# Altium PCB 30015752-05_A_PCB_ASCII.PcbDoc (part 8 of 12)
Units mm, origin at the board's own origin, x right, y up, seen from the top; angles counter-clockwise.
Board outline 100.05 x 72 mm, 10 copper layers (Top, GND_2, Signal_3, Signal_4, PWR_5, GND_6, Signal_7, Signal_8, GND_9, Bottom), stack 1.493 mm thick; 577 components, 546 nets, 2389 pads, 1412 vias.
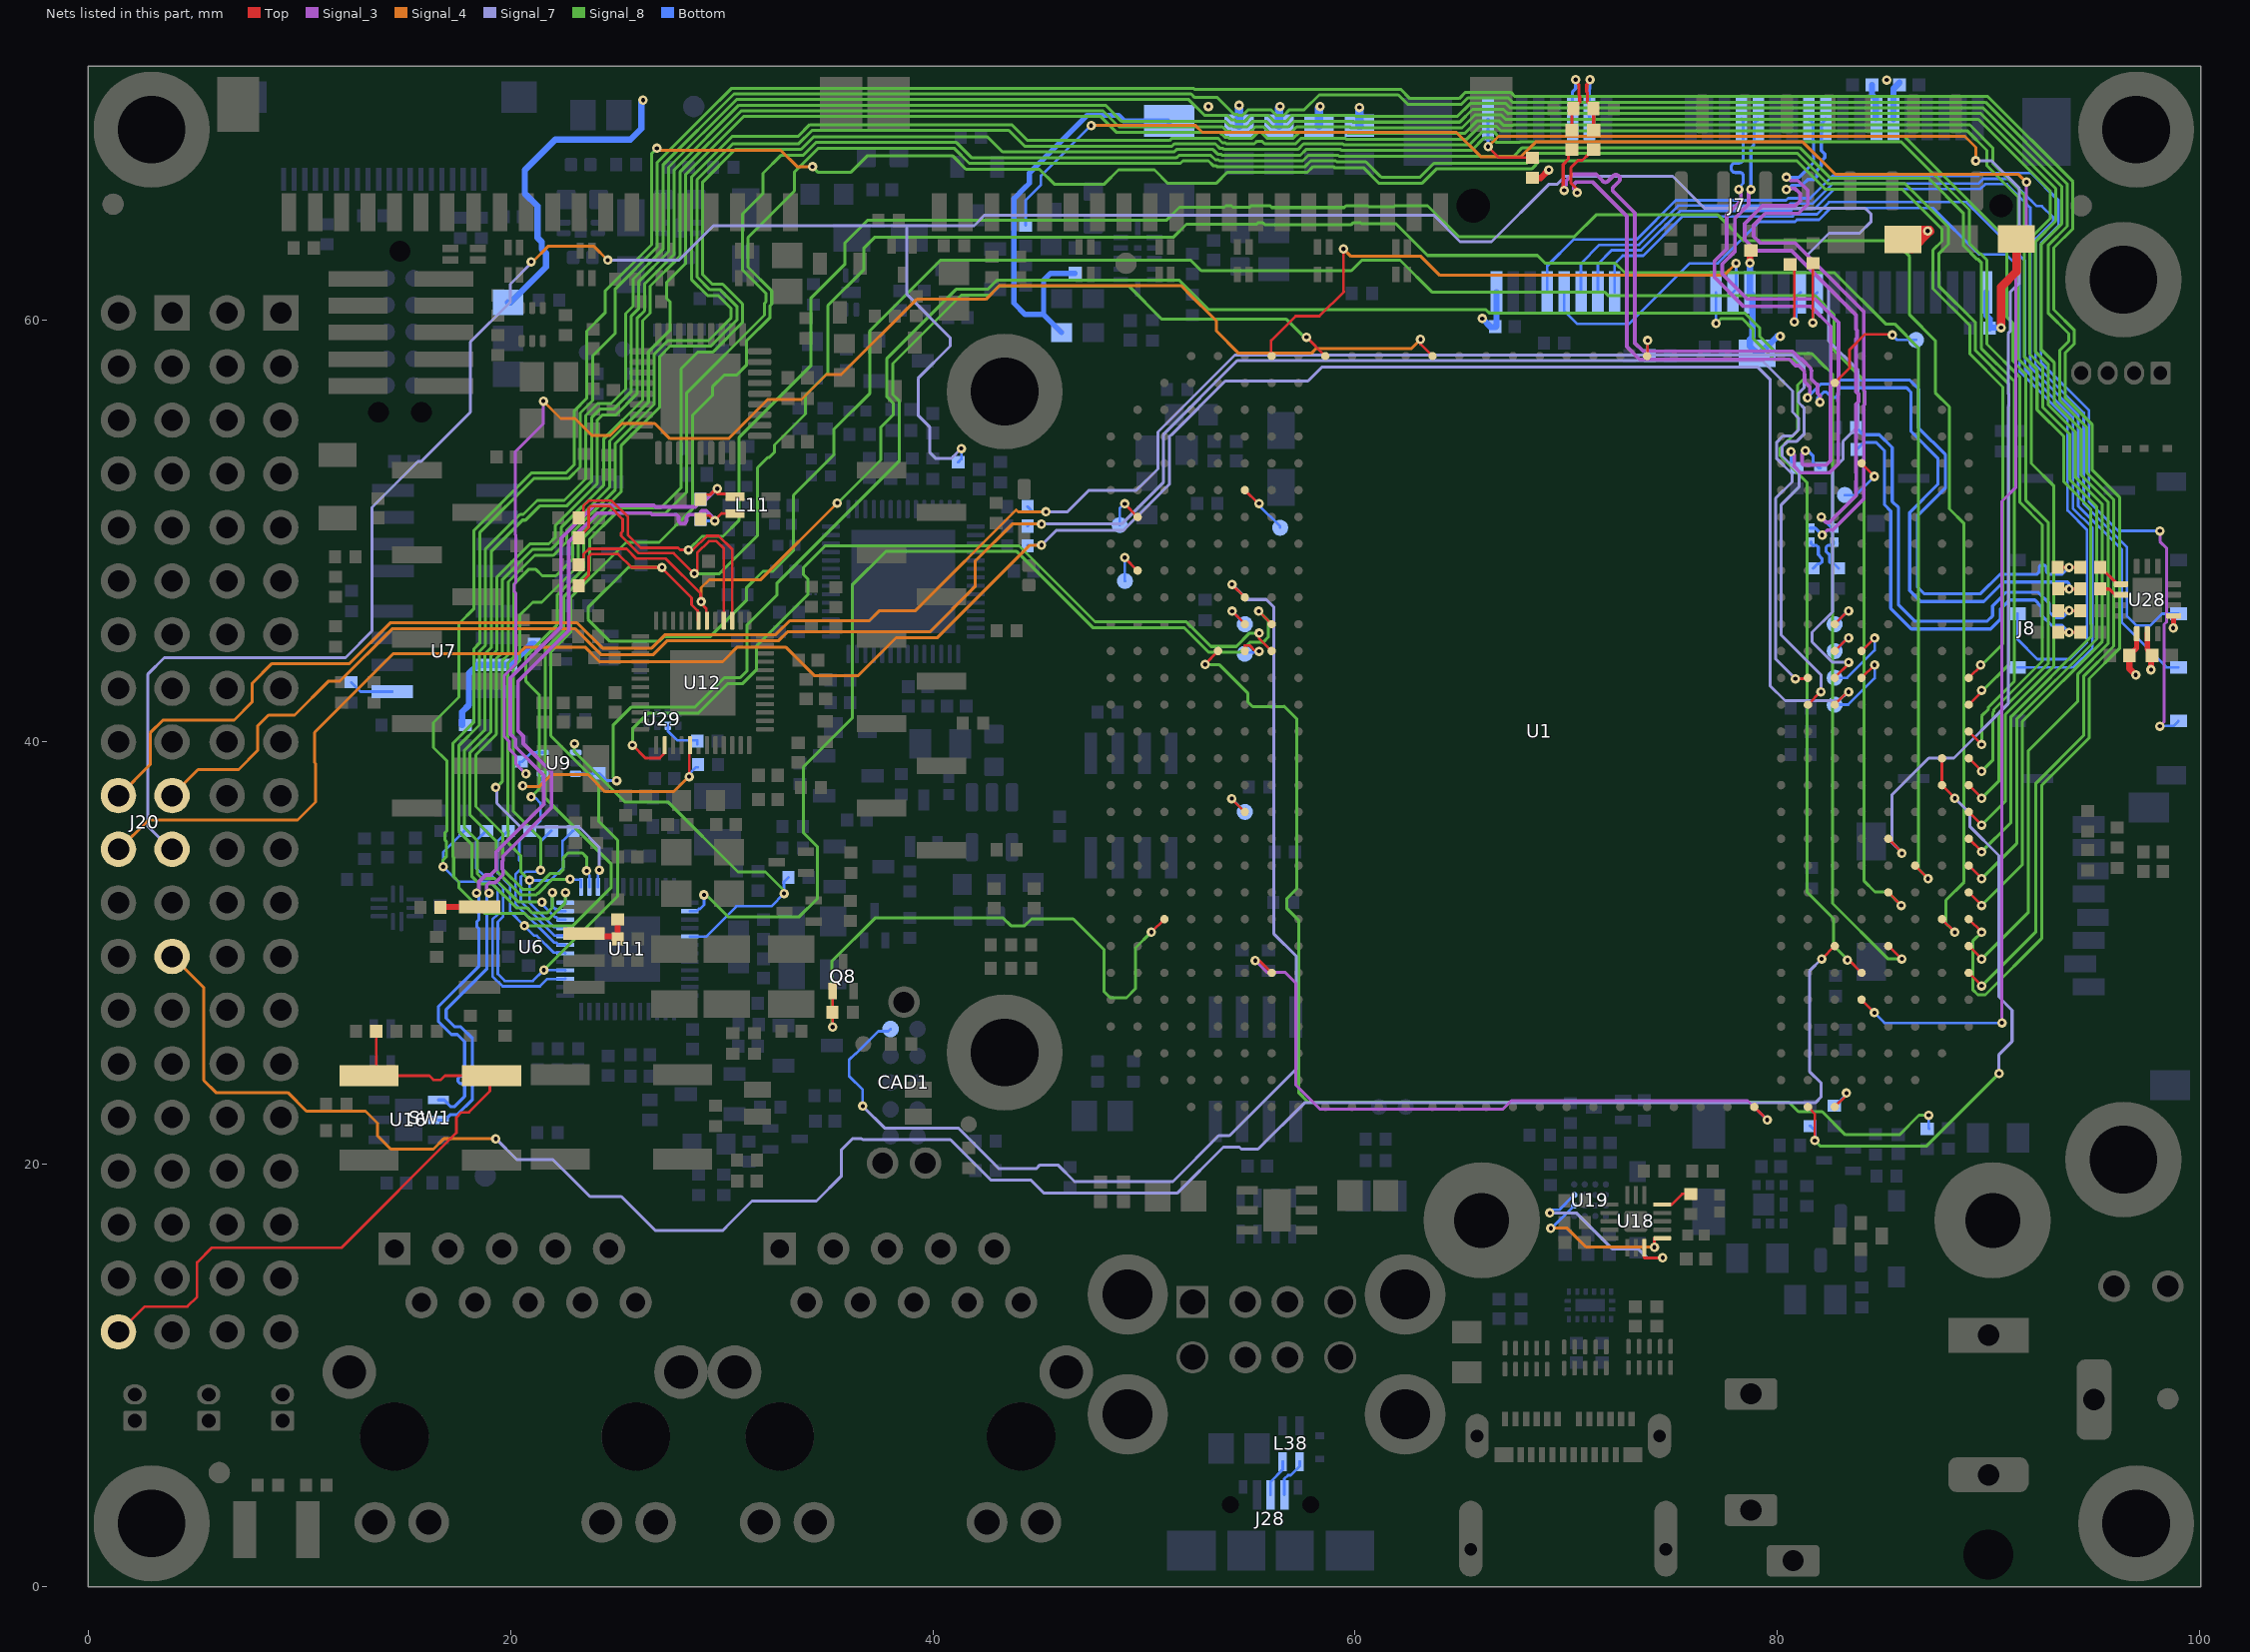
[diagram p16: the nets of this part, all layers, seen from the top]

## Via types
v1: diameter 0.45, hole 0.2, Top to Bottom, tented both sides, 1412 vias

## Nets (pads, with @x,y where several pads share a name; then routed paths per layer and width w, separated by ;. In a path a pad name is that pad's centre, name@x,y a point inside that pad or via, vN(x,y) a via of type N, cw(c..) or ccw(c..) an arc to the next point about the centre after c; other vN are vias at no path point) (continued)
NetR230_2: R230.2 R231.1 U1.N1 | length 1.5
  Top w0.127: U1.N1@73.83,58.28 73.86,58.31 v1(73.86,59.02)
  Bottom w0.127: v1(73.86,59.02) 73.86,58.46 73.83,58.43 R231.1@73.96,58.3
NetR232_2: R232.2 U1.F29 | length 1.7
  Top w0.127: U1.F29@82.72,22.72 83.275,23.275 v1(83.275,23.375)
  Bottom w0.127: R232.2@82.7,22.78 82.725,22.78 83.275,23.33 v1(83.275,23.375)
NetR234_1: R234.1 U18.5 | length 1.6
  Top w0.127: U18.5@74.55,18.1 75,18.1 75.5,18.6 R234.1@75.9,18.6
NetR236_1: R236.1 U28.8 | length 1.3
  Top w0.15: R236.1@95.305,48.275 96.105,47.475 U28.8@96.275,47.475
NetR237_1: R237.1 U28.9 | length 1.1
  Top w0.15: R237.1@95.305,47.25 95.725,47.25 96,46.975 U28.9@96.275,46.975
NetR244_2: R244.2 U29.6 | length 2
  Bottom w0.127: U29.6@27.45,40.775 27.45,40.525 27.9,40.075 28.845,40.075 R244.2@28.845,40.05 R244.2@28.845,39.9
NetR245_2: R245.2 R246.2 U6.3 | length 2.6
  Top w0.3: U6.3@23.47,30.925 23.595,30.8 24.945,30.8 R246.2@25.07,30.675 25.075,30.68 R245.2@25.075,31.595
NetR247_1: R247.1 U6.5 | length 1.9
  Top w0.3: R247.1@16.68,32.175 16.7,32.195 U6.5@18.53,32.195
NetR248_2: R248.2 R249.2 U7.3 | length 6.3
  Bottom w0.3: R248.2@17.7,40.805 17.7,41.425 18.025,41.75 18.025,43.25 18.431,43.656 U7.3@19.329,43.656 20.006,43.656 21.005,44.655 R249.2@21.125,44.655
NetR250_1: R250.1 U7.5 | length 2.1
  Bottom w0.127: R250.1@12.45,42.83 12.894,42.386 U7.5@14.389,42.386
NetTP3_1: TP3.1 U1.AH6 | length 2.5
  Top w0.127: U1.AH6@54.78,51.93 55.41,51.3 v1(55.45,51.3)
  Bottom w0.127: v1(55.45,51.3) 55.45,51.213 56.45,50.213 TP3.1@56.45,50.15
NetTP4_1: TP4.1 U1.AH11 | length 1.7
  Top w0.127: v1(54.175,46.2) 54.78,45.595 U1.AH11@54.78,45.58
  Bottom w0.127: v1(54.175,46.2) 54.175,46.193 54.78,45.588 TP4.1@54.78,45.58
NetTP5_1: TP5.1 U1.AH12 | length 1.8
  Top w0.127: U1.AH12@54.78,44.31 54.78,44.573 55.012,44.573 55.285,44.3 v1(55.45,44.3)
  Bottom w0.127: TP5.1@54.775,44.175 54.838,44.238 55.388,44.238 v1(55.45,44.3)
NetTP6_1: TP6.1 U1.AM7 | length 2
  Top w0.127: v1(49.09,51.28) 49.09,51.27 U1.AM7@49.7,50.66
  Bottom w0.127: TP6.1@48.85,50.275 48.85,51.057 49.073,51.28 v1(49.09,51.28)
NetTP7_1: TP7.1 U1.AM9 | length 2
  Top w0.127: v1(49.09,48.74) 49.09,48.73 U1.AM9@49.7,48.12
  Bottom w0.127: v1(49.09,48.74) 49.09,47.635 TP7.1@49.1,47.625
NetTP8_1: TP8.1 U1.F2 | length 5.4
  Top w0.127: U1.F2@82.72,57.01 83.425,57.715 83.425,58.575 84.162,59.312 85.413,59.312 v1(85.45,59.275)
  Bottom w0.127: v1(85.45,59.275) 85.677,59.048 TP8.1@86.575,59.048
NetTP9_1: TP9.1 U1.E5 | length 2.6
  Top w0.127: U1.E5@83.99,53.2 84.6,52.59 v1(84.6,52.58)
  Bottom w0.127: TP9.1@83.2,51.7 83.72,51.7 v1(84.6,52.58)
NetTP10_1: TP10.1 U1.AH18 | length 1.8
  Top w0.127: v1(54.16,37.32) 54.16,37.31 U1.AH18@54.78,36.69
  Bottom w0.127: v1(54.16,37.32) 54.16,37.315 54.78,36.695 TP10.1@54.78,36.69
NetTP18_1: TP18.1 U1.E13 | length 3.9
  Top w0.127: U1.E13@83.99,43.04 84.6,43.65 v1(84.61,43.65)
  Bottom w0.127: TP18.1@82.72,41.77 83.36,41.77 84.61,43.02 v1(84.61,43.65)
NetTP19_1: TP19.1 U1.E12 | length 3.9
  Top w0.127: U1.E12@83.99,44.31 84.6,44.92 v1(84.61,44.92)
  Bottom w0.127: TP19.1@82.72,43.04 83.303,43.04 84.61,44.347 v1(84.61,44.92)
NetTP20_1: TP20.1 U1.F12 | length 1.7
  Top w0.127: U1.F12@82.72,44.31 83.33,44.92 v1@83.34,44.92
  Bottom w0.127: TP20.1@82.72,44.31 82.725,44.31 83.335,44.92 v1@83.34,44.92
  other v1: 83.379,44.927
NetTP21_1: TP21.1 U1.F11 | length 1.7
  Top w0.127: U1.F11@82.72,45.58 83.33,46.19 v1@83.34,46.19
  Bottom w0.127: TP21.1@82.72,45.58 82.725,45.58 83.335,46.19 v1@83.34,46.19
  other v1: 83.379,46.202
NetU1_AG24: U1.AG24 U1.J29 | length 32.4
  Top w0.127: v1(55.275,29.65) 55.47,29.65 U1.AG24@56.05,29.07 ; U1.J29@78.91,22.72 79.52,22.11 v1(79.52,22.1)
  Signal_3 w0.142: v1(55.275,29.65) 55.825,29.1 56.675,29.1 57.2,28.575 57.2,23.75 58.333,22.617 66.997,22.617 67.398,23.019 78.601,23.019 v1(79.52,22.1)
NX5P3290_EN: U18.16 U19.B4 | length 9.1
  Top w0.127: U18.16@73.7,16.05 73.7,15.567 74.567,15.567 v1(74.575,15.575)
  Signal_7 w0.142: v1(69.225,17.7) 70.475,17.7 72.175,16 73.4,16 73.825,15.575 v1(74.575,15.575)
  Bottom w0.127: v1(69.225,17.7) 69.372,17.847 69.674,17.847 70.376,18.55 U19.B4@70.38,18.55
NX5P3290_FRS: U18.1 U19.C4 | length 7.7
  Top w0.127: v1(74.175,16.075) 74.175,16.475 74.2,16.5 U18.1@74.55,16.5
  Signal_4 w0.142: v1(69.275,16.975) 70.05,16.975 70.95,16.075 v1(74.175,16.075)
  Bottom w0.127: v1(69.275,16.975) 69.275,16.942 69.283,16.934 v1@69.288,16.939 ; v1@69.324,16.975 v1@69.288,16.939 ; U19.C4@70.38,18.05 69.278,16.948 v1@69.288,16.939
OTGD_N: J28.2 L38.2 | length 2
  Bottom w0.132: J28.2@56.65,4.35 56.65,5.104 56.828,5.282 56.957,5.282 57.375,5.7 L38.2@57.375,5.925
OTGD_P: J28.3 L38.3 | length 1.8
  Bottom w0.132: J28.3@56,4.35 56,4.975 56.575,5.55 L38.3@56.575,5.925
PCIe/EXPANSION_USB1_D_N: L11.2 R192.1 R229.1 U16.1 | length 44.8
  Top w0.132: R192.1@29.005,51.5 29.224,51.719 29.458,51.719 29.744,52.005 v1(29.788,52.005) 29.788,51.877 29.736,51.825 29.811,51.75 30.5,51.75 L11.2@30.625,51.625
  Signal_3 w0.175: v1(18.396,32.85) 18.5,32.954 18.5,33.378 18.833,33.71 19.057,33.71 19.308,33.961 19.308,34.482 19.315,34.489 19.315,34.79 21.575,37.05 21.575,38.429 20.232,39.772 20.232,40.132 19.992,40.371 19.992,43.042 22.382,45.432 22.382,49.632 23.958,51.208 26.785,51.208 26.857,51.135 28.74,51.135 28.938,51.334 29.117,51.334 v1(29.788,52.005)
  Bottom w0.132: R229.1@29.005,51.5 29.224,51.719 29.458,51.719 29.744,52.005 v1(29.788,52.005)
  Bottom w0.15: U16.1@16.575,23.05 16.85,23.05 17.175,22.725 17.329,22.725 17.825,23.221 17.825,23.65 17.825,23.667 ccw(c17.668,23.667) 17.668,23.825 cw(c17.668,23.982) 17.51,23.982 17.51,24.017 cw(c17.668,24.017) 17.668,24.175 ccw(c17.668,24.332) 17.825,24.332 17.825,24.625 17.825,25.804 17.479,26.15 17.197,26.15 16.582,26.766 16.582,27.478 18.5,29.396 18.5,31.15 18.4,31.25 18.4,31.5 18.5,31.6 18.5,31.9 18.325,32.075 18.325,32.25 18.5,32.425 18.5,32.746 v1(18.396,32.85)
PCIe/EXPANSION_USB1_D_P: L11.3 R191.1 R228.1 U16.2 | length 44.2
  Top w0.132: R191.1@29.005,50.55 29.18,50.725 29.425,50.725 29.613,50.538 29.65,50.5 v1@29.65,50.475 ; v1(29.675,50.475) v1@29.65,50.475 ; L11.3@30.625,50.825 30,50.825 29.662,50.487 v1@29.65,50.475
  Signal_3 w0.175: v1(18.973,32.85) 18.868,32.954 18.868,33.225 18.987,33.344 19.273,33.344 19.643,33.714 19.643,33.96 19.61,33.993 19.61,34.357 19.643,34.39 19.643,34.597 21.943,36.897 21.943,38.582 20.6,39.925 20.6,40.284 20.36,40.524 20.36,42.89 22.75,45.279 22.75,49.479 24.11,50.84 26.632,50.84 26.705,50.767 27.575,50.767 27.793,50.767 cw(c27.793,50.598) 27.962,50.598 27.962,50.51 ccw(c28.131,50.51) 28.131,50.342 28.169,50.342 ccw(c28.169,50.51) 28.337,50.51 28.337,50.598 cw(c28.506,50.598) 28.506,50.767 28.525,50.767 28.892,50.767 29.091,50.966 29.25,50.966 29.675,50.541 v1(29.675,50.475)
  Bottom w0.132: R228.1@29.005,50.45 29.03,50.475 v1(29.675,50.475)
  Bottom w0.15: U16.2@16.575,22.1 16.9,22.1 17.157,22.357 17.482,22.357 18.193,23.068 18.193,25.957 17.632,26.518 17.35,26.518 16.95,26.918 16.95,27.325 18.868,29.243 18.868,32.746 v1(18.973,32.85)
PCIE_CLK_N: C139.1 R195.2 R237.2 | length 49.8
  Top w0.15: v1(69.903,66.128) 69.903,66.203 69.85,66.256 69.886,66.293 69.857,66.322 69.857,67.353 70.106,67.602 C139.1@70.106,67.896 ; R195.2@93.28,47.25 R195.2@93.305,47.25 v1(93.825,47.25) R237.2@94.345,47.25
  Signal_3 w0.175: v1(69.903,66.128) 69.903,66.196 69.85,66.249 69.993,66.393 69.993,66.567 70.312,66.886 71.417,66.886 71.727,66.577 71.74,66.563 ccw(c71.859,66.683) 71.979,66.563 72.231,66.816 cw(c72.35,66.696) 72.47,66.816 72.496,66.789 cw(c72.377,66.67) 72.496,66.55 72.244,66.298 ccw(c72.363,66.178) 72.244,66.059 72.364,65.939 73.25,65.053 73.25,58.9 73.65,58.5 80.719,58.5 81.083,58.136 81.151,58.136 81.586,57.701 81.586,57.633 81.636,57.583 81.61,57.557 81.61,57.193 81.868,56.935 81.909,56.935 81.909,56.515 82.025,56.399 v1(82.025,56.1)
  Bottom w0.15: v1(82.025,56.1) 81.9,56.225 81.9,56.279 82.201,56.58 82.325,56.58 82.58,56.325 82.775,56.325 82.893,56.443 82.893,56.497 82.893,56.718 82.952,56.777 86.123,56.777 86.332,56.568 86.332,54.718 87.6,53.45 87.6,52.2 86.275,50.875 86.275,47.175 86.793,46.657 89.782,46.657 90.703,47.578 93.747,47.578 93.825,47.5 v1(93.825,47.25)
PCIE_CLK_P: C140.1 R112.2 R236.2 | length 48.5
  Top w0.15: v1(70.52,66.02) 70.52,66.18 70.225,66.475 70.225,67.2 70.575,67.55 70.77,67.55 71.059,67.84 71.075,67.84 C140.1@71.3,68.065 ; R112.2@93.28,48.275 v1(93.825,48.275) R236.2@94.345,48.275
  Signal_3 w0.175: 70.362,66.188 70.362,66.415 70.464,66.517 71.265,66.517 72.875,64.907 72.875,58.725 73.468,58.132 80.566,58.132 80.865,57.833 81.026,57.833 81.283,57.576 81.283,57.415 81.294,57.404 81.294,57.062 81.541,56.815 81.541,56.515 81.38,56.354 81.429,56.305 v1(81.429,56.303)
  Bottom w0.15: v1@81.4,56.3 v1@81.403,56.303 ; v1(81.429,56.303) v1@81.403,56.303 ; v1(93.825,48.275) 93.497,47.947 93.277,47.947 93.102,47.947 92.91,47.947 cw(c92.91,48.104) 92.752,48.104 92.752,48.226 ccw(c92.595,48.226) 92.595,48.383 92.56,48.383 ccw(c92.56,48.226) 92.402,48.226 92.402,48.104 cw(c92.245,48.104) 92.245,47.947 91.825,47.947 90.551,47.947 89.629,47.025 86.946,47.025 86.643,47.328 86.643,50.722 87.968,52.047 87.968,53.603 86.7,54.871 86.7,56.721 86.276,57.145 82.799,57.145 82.602,56.948 82.048,56.948 81.416,56.316 v1@81.403,56.303
PCIE_DIS_N: J7.20 U1.E24 | length 37.6
  Top w0.127: v1(83.325,29.675) 83.385,29.675 U1.E24@83.99,29.07
  Signal_8 w0.142: v1(77.1,59.825) 77.325,60.05 78.35,60.05 78.85,59.55 78.85,59.125 79.85,58.125 80.711,58.125 81.267,57.569 81.267,57.218 80.957,56.908 80.957,54.732 80.125,53.9 80.125,53.57 81.42,52.275 81.42,32.88 82.675,31.625 82.675,30.35 83.325,29.7 v1(83.325,29.675)
  Bottom w0.127: v1(77.1,59.825) J7.20@77.1,61.3
PCIE_I2C_SCL: J7.30 R177.2 | length 4.4
  Top w0.127: R177.2@80.6,62.62 80.8,62.42 80.76,62.38 80.804,62.336 v1(80.804,59.903)
  Bottom w0.127: v1(80.804,59.903) 80.889,59.987 80.889,61.089 J7.30@81.1,61.3
PCIE_I2C_SDA: J7.32 R178.2 | length 4.4
  Top w0.127: v1(81.686,59.86) 81.686,62.606 81.7,62.62 81.675,62.645 R178.2@81.7,62.67
  Bottom w0.127: v1(81.686,59.86) 81.689,59.862 81.689,61.089 J7.32@81.9,61.3
PCIE_RESET_N: J7.22 U1.AG1 | length 28
  Top w0.127: U1.AG1@56.05,58.28 56.024,58.306 56.024,59.012 57.186,60.174 58.312,60.174 59.475,61.337 59.453,61.359 v1(59.453,63.353)
  Signal_4 w0.142: v1(59.453,63.353) 59.806,63 63.122,63 64.018,62.104 77.479,62.104 v1(78.05,62.675)
  Bottom w0.127: J7.22@77.9,61.3 78.05,61.45 v1(78.05,62.675)
PCIE_RX_N: J7.23 R227.1 | length 25.1
  Signal_3 w0.175: v1(78.173,66.175) 78.277,66.071 78.277,65.652 77.6,64.975 77.6,63.35 77.025,62.775 77.025,62.015 78.413,60.627 81.598,60.627 82.532,59.693 82.532,56.86 82.525,56.853 82.525,53.325 82.325,53.125 81.247,53.125 81.172,53.2 81.172,53.647 v1(81.325,53.8)
  Bottom w0.15: v1@78.173,66.256 78.382,66.465 78.382,66.825 ccw(c78.231,66.825) 78.231,66.975 78.012,66.975 cw(c78.012,67.178) 77.81,67.178 77.81,67.223 cw(c78.012,67.223) 78.012,67.425 78.179,67.425 ccw(c78.179,67.628) 78.382,67.628 78.382,67.875 78.382,68.1 78.382,69.39 78.396,69.404 J7.23@78.3,69.5 ; v1(81.325,53.8) 81.45,53.8 81.691,53.559 81.691,53.259 81.97,52.98 R227.1@82.05,52.98
PCIE_RX_P: J7.25 R226.1 | length 25.2
  Signal_3 w0.175: v1(78.75,66.175) 78.646,66.071 78.646,65.471 78,64.825 78,63.247 77.393,62.64 77.393,62.168 78.566,60.995 81.78,60.995 82.9,59.875 82.9,56.707 82.893,56.7 82.893,56.515 82.88,56.502 82.88,56.138 82.893,56.125 82.893,53.172 82.478,52.757 81.094,52.757 80.803,53.047 80.803,53.597 v1(80.65,53.75)
  Bottom w0.15: v1(78.75,66.175) 78.75,68.141 78.884,68.275 78.884,68.487 78.9,68.503 78.9,69.3 J7.25@79.1,69.5 ; v1(80.65,53.75) 80.65,53.18 R226.1@80.85,52.98
PCIE_SOM_CLK_N: R111.2 R117.1 R223.1 | length 20.9
  Top w0.15: R117.1@93.28,46.225 R117.1@93.305,46.225 v1(93.825,46.225) R111.2@94.345,46.225
  Bottom w0.15: R223.1@83.735,54.9 84.076,54.559 84.837,54.559 85.443,53.953 85.443,51.394 85.743,51.094 85.743,46.482 86.5,45.725 89.95,45.725 90.2,45.975 90.2,46.45 90.843,47.093 92.353,47.093 92.868,46.578 92.868,46.172 93.14,45.9 93.5,45.9 v1(93.825,46.225)
PCIE_SOM_CLK_P: R30.1 R110.2 R222.1 | length 20.9
  Top w0.15: R30.1@93.28,45.2 R30.1@93.305,45.2 v1(93.825,45.2) R110.2@94.345,45.2
  Bottom w0.15: R222.1@83.748,53.85 84.088,54.191 84.684,54.191 85.075,53.8 85.075,51.241 85.375,50.941 85.375,46.329 86.347,45.357 90.103,45.357 90.568,45.822 90.568,46.297 90.996,46.725 92.2,46.725 92.5,46.425 92.5,46.019 92.987,45.532 93.493,45.532 v1(93.825,45.2)
PCIE_TX_N: C138.1 J7.31 | length 28.2
  Signal_3 w0.175: v1(80.425,66.75) 80.47,66.75 80.626,66.593 80.978,66.593 81.443,66.128 81.443,65.472 81,65.029 79.429,65.029 78.882,64.482 78.882,63.943 79.182,63.643 80.828,63.643 84.101,60.37 84.101,56.655 84.146,56.61 84.146,55.995 84.101,55.95 84.101,51.529 82.613,50.041 82.365,50.041 v1@82.125,49.801
  Bottom w0.15: v1(80.425,66.75) 80.506,66.75 80.534,66.722 80.556,66.743 81.022,66.743 81.716,67.437 81.716,68.487 81.7,68.503 81.7,69.3 J7.31@81.5,69.5 ; C138.1@81.55,50.13 81.795,50.13 v1(82.125,49.8)
PCIE_TX_P: C137.1 J7.33 | length 28.2
  Signal_3 w0.175: v1(80.425,66.173) 80.477,66.225 80.825,66.225 81.075,65.975 81.075,65.625 80.847,65.397 79.297,65.397 78.45,64.55 78.45,63.8 78.975,63.275 80.675,63.275 83.725,60.225 83.725,59.557 83.78,59.502 83.78,59.138 83.725,59.083 83.725,56.604 83.844,56.485 83.844,56.121 83.725,56.002 83.725,52.753 83.744,52.735 83.744,52.37 83.725,52.352 83.725,51.674 82.46,50.409 82.315,50.409 82.075,50.649 82.08,50.654 v1(82.08,50.66)
  Bottom w0.15: v1(80.425,66.173) 80.506,66.173 80.708,66.375 81.175,66.375 81.437,66.638 81.738,66.638 81.875,66.775 81.875,67.075 82.084,67.285 82.084,67.509 82.25,67.675 82.25,67.85 82.084,68.016 82.084,68.487 82.1,68.503 82.1,69.3 J7.33@82.3,69.5 ; v1(82.08,50.66) 82.08,50.645 82.595,50.13 C137.1@82.65,50.13
PCIE_UIM_CLK: J7.12 J8.3 | length 50
  Bottom w0.127: J7.12@70.7,61.3 70.7,62.665 71.581,63.546 73.44,63.546 75.3,65.406 79.842,65.406 ; 79.842,65.406 80.515,65.406 80.613,65.503 81.663,65.503 82.607,66.447 89.52,66.447 89.751,66.679 90.993,66.679 92.039,65.633 92.039,65.631 92.286,65.384 92.528,65.384 93.066,64.847 93.066,64.665 92.238,63.838 92.238,57.864 94.512,55.591 94.512,51.279 96.563,49.228 96.563,45.962 97,45.525 97.675,45.525 98.23,46.08 J8.3@99,46.08
PCIE_UIM_DATA: J7.10 J8.7 | length 50.4
  Bottom w0.127: J7.10@69.9,61.3 69.9,60.425 70.525,59.8 72.975,59.8 75.85,62.675 77.175,62.675 79.144,64.644 79.526,64.644 80.831,64.644 80.929,64.741 81.979,64.741 82.531,65.294 87.359,65.294 89.552,63.1 90.825,63.1 91.476,62.449 91.476,57.549 93.75,55.275 93.75,50.963 94.675,50.038 94.675,44.725 93.875,43.925 92.325,43.925 91.38,44.87 J8.7@91.38,46.08
PCIE_UIM_PWR: J7.8 J8.1 | length 57.8
  Signal_3 w0.142: v1(98.125,40.75) 98.327,40.952 98.327,45.575 98.448,45.697 98.448,49.175 98.125,49.498 v1(98.125,50)
  Bottom w0.127: J7.8@69.1,61.3 69.1,62.55 70.35,63.8 73.335,63.8 75.194,65.66 79.947,65.66 80.41,65.66 80.508,65.757 81.558,65.757 82.616,66.816 89.529,66.816 89.657,66.944 92.024,66.944 93.32,65.648 93.32,64.444 92.492,63.617 92.492,57.969 94.766,55.696 94.766,51.384 96.15,50 v1(98.125,50) ; v1(98.125,40.75) 98.139,40.763 98.764,40.763 J8.1@99,41
PCIE_UIM_RST: J7.14 J8.2 | length 48.9
  Bottom w0.127: J7.14@71.5,61.3 71.5,62.641 72.151,63.292 73.545,63.292 75.405,65.152 79.736,65.152 80.62,65.152 80.718,65.249 81.768,65.249 82.712,66.193 89.625,66.193 89.857,66.425 90.875,66.425 91.984,65.316 91.984,57.759 94.258,55.485 94.258,51.174 96.309,49.122 96.309,45.666 98.435,43.54 J8.2@99,43.54
PCIE_UIM_VPP: J7.16 J8.6 | length 46.7
  Bottom w0.127: J7.16@72.3,61.3 72.3,62.665 72.673,63.038 73.65,63.038 75.51,64.898 79.631,64.898 80.726,64.898 80.824,64.995 81.874,64.995 82.448,65.57 88.955,65.57 91.73,62.794 91.73,57.654 94.004,55.38 94.004,51.068 94.929,50.143 94.929,44.454 94.015,43.54 J8.6@91.38,43.54
PCIE_VCC: C14.2 C15.2 C16.2 C17.2 C18.2 C19.1 C20.1 C21.1 C22.2 C23.2 C24.2 C25.2 C26.2 C46.1 C64.1 J7.2 J7.24 J7.39 J7.41 J7.52 L1.2 L23.1 R49.2 R52.2 U28.1 U28.12 U28.13 | length 67.4
  Top w0.25: C46.1@96.75,44.175 97.025,44.45 U28.12@97.025,45.125 ; U28.13@97.525,45.125 97.525,44.4 C64.1@97.7,44.225 ; v1(98.75,45.4) 98.775,45.425 U28.1@98.775,45.975
  Top w0.3: R52.2@68.4,66.72 68.8,66.72 v1(69.18,67.1) ; v1(78.7,62.68) C22.2@78.7,63.29 ; C46.1@96.675,44.1 96.675,43.475 v1(96.975,43.175) ; v1(97.705,43.427) 97.705,44.05 C64.1@97.755,44.1
  Top w0.4: v1(87.125,64.2) v1(87.125,64.2) 87.173,64.25 87.237,64.187 86.4,63.35 C20.1@85.95,63.8 86.403,64.253 v1@87.229,64.253 ; v1(90.604,59.628) 90.604,61.554 91.325,62.275 C21.1@91.325,63.825
  Bottom w0.25: R49.2@46.1,59.4 45.25,60.25 ; C14.2@46.74,62.2 45.575,62.2 45.25,61.875 45.25,60.25 ; L1.2@51.2,69.35 51.125,69.425 49.05,69.425 48.798,69.677 47.302,69.677 44.577,66.952 44.577,66.477 44.298,66.198 43.838,65.738 43.838,60.787 44.375,60.25 45.25,60.25
  Bottom w0.3: L23.1@19.875,60.825 20,60.825 21.677,62.502 21.677,63.154 21.477,63.354 21.477,63.683 21.273,63.887 21.273,65.383 20.673,65.983 20.673,67.083 22.117,68.527 25.669,68.527 26.198,69.056 26.198,70.323 v1(26.275,70.4) ; v1@66.018,60.057 66.425,59.65 66.64,59.65 66.7,59.71 J7.2@66.7,61.3 ; v1(78.7,62.68) J7.24@78.7,61.3 78.827,61.173 78.827,59.196 78.7,59.069 78.7,58.75 C19.1@79.05,58.4 79.175,58.4 79.995,59.22 v1(80.14,59.22) ; C23.2@84.485,71.125 84.485,70.64 84.66,70.465 J7.39@84.66,69.54 ; J7.41@85.5,69.5 85.5,70.95 C26.2@85.79,71.24 ; J7.52@89.9,61.3 89.9,60.2 90.06,60.04 C24.2@90.06,59.6 90.088,59.628 v1(90.604,59.628)
  Bottom w0.4: C18.2@54.5,69.2 54.503,69.203 v1(54.503,70.153) ; C17.2@56.4,69.2 56.4,70.05 v1(56.45,70.1) ; C16.2@58.3,69.2 58.3,70.05 v1(58.35,70.1) ; C15.2@60.2,69.2 60.2,70.05 v1(60.203,70.053)
  other v1: 66.02,60.06 53.053,70.103 85.179,71.353
PCIE_VCC_EN: R45.1 U1.E25 | length 99.4
  Top w0.127: U1.E25@83.99,27.8 83.99,27.795 84.6,27.185 v1(84.6,27.18)
  Signal_3 w0.142: v1(90.64,26.7) 90.64,51.396 91.288,52.045 91.288,63.21 91.804,63.726 v1(91.804,66.528)
  Signal_4 w0.142: v1(47.5,69.2) 52.454,69.2 52.773,68.881 64.796,68.881 65.954,67.723 67.856,67.723 68.553,68.42 81.205,68.42 82.73,66.895 91.405,66.895 91.78,66.52 91.788,66.528 v1(91.804,66.528)
  Bottom w0.127: R45.1@44.4,64.475 44.4,65.661 45.123,66.384 45.123,66.823 v1(47.5,69.2) ; v1(84.6,27.18) 85.08,26.7 v1(90.64,26.7)
PCIE_WAKE_N: J7.1 R52.1 U1.D19 | length 66.3
  Top w0.127: v1(66.3,68.2) 66.82,67.68 R52.1@68.4,67.68 ; U1.D19@85.26,35.42 85.904,34.776 v1(85.904,34.727)
  Signal_4 w0.142: v1(66.3,68.2) 66.79,68.69 88.885,68.69 89.404,68.171 v1(89.404,67.528)
  Signal_7 w0.142: v1(85.904,34.727) 85.904,34.776 85.425,35.255 85.425,37.493 87.171,39.24 88.368,39.24 90.937,41.808 90.937,55.897 90.956,55.917 90.956,56.491 90.937,56.51 90.937,59.352 91.031,59.446 91.031,61.312 91.469,61.75 91.469,66.212 90.152,67.528 v1(89.404,67.528)
  Bottom w0.127: v1(66.3,68.2) J7.1@66.3,69.5
PCIECLK_N: C139.2 J7.11 R218.2 | length 4.6
  Top w0.15: C139.2@70.275,68.985 70.275,69.923 R218.2@70.352,70 70.352,70.025 70.638,70.311 70.638,70.604 70.603,70.638 70.603,71.14 70.45,71.294 v1(70.45,71.375)
  Bottom w0.15: J7.11@70.3,69.5 70.3,70.797 70.45,70.947 v1(70.45,71.375)
PCIECLK_P: C140.2 J7.13 R217.2 | length 4.5
  Top w0.15: v1(71.125,71.375) 71.125,71.294 70.972,71.14 70.972,70.791 71.006,70.756 71.006,70.311 71.292,70.025 R217.2@71.292,70 71.3,69.992 C140.2@71.3,68.985
  Bottom w0.15: J7.13@71.1,69.5 71.1,70.91 71.125,70.935 v1(71.125,71.375)
PCIETX_N: C138.2 R225.1 | length 1.8
  Bottom w0.15: C138.2@81.6,49.47 81.6,49.4 81.685,49.315 81.853,49.315 81.941,49.227 81.941,48.87 82.116,48.695 82.116,48.528 82.028,48.44 81.91,48.44 R225.1@81.7,48.23
PCIETX_P: C137.2 R224.1 | length 1.8
  Bottom w0.15: C137.2@82.65,49.47 82.65,49.4 82.565,49.315 82.397,49.315 82.309,49.227 82.309,49.022 82.484,48.847 82.484,48.528 82.572,48.44 82.69,48.44 R224.1@82.9,48.23
PCM_CLK: J20.19 R155.1 U1.G13 | length 106.4
  Top w0.127: v1(80.85,43) 81.41,43 U1.G13@81.45,43.04
  Signal_4 w0.142: J20.19@3.965,37.465 5.199,38.699 7.116,38.699 8.031,39.614 8.031,40.775 8.531,41.275 9.771,41.275 11.385,42.89 11.926,42.89 14.412,45.375 23.05,45.375 24.3,44.125 26.745,44.125 27.425,44.805 32.7,44.805 33.125,45.23 39.87,45.23 41.999,47.359 41.999,48.559 43.765,50.325 v1(45.15,50.325)
  Signal_7 w0.142: v1(45.15,50.325) 48.944,50.325 50.931,52.312 50.931,54.577 54.417,58.063 79.283,58.063 80.723,56.623 80.723,55.627 81,55.35 81,54.775 80.719,54.494 80.269,54.494 79.958,54.183 79.958,53.438 80.698,52.698 80.698,52.325 79.92,51.547 79.92,43.93 v1(80.85,43)
  Bottom w0.127: R155.1@44.48,50.225 44.58,50.325 v1(45.15,50.325)
PCM_IN: J20.20 R158.1 U1.G14 | length 111.8
  Top w0.127: U1.G14@81.45,41.77 82.06,42.38 v1(82.07,42.38)
  Signal_4 w0.142: J20.20@1.46,37.46 2.929,38.929 2.929,40.434 3.536,41.041 6.903,41.041 7.762,41.9 7.762,42.779 8.7,43.717 12.371,43.717 14.298,45.644 23.162,45.644 24.356,44.45 26.69,44.45 27.328,45.089 32.564,45.089 33.225,45.75 36.99,45.75 37.45,46.21 39.16,46.21 43.95,51 44.048,50.902 v1(45.36,50.902)
  Signal_7 w0.142: v1(45.36,50.902) 46.377,50.902 47.4,51.925 49.65,51.925 50.661,52.936 50.661,54.689 54.305,58.332 80.718,58.332 81.275,57.775 81.275,56.793 81.006,56.524 81.006,56.076 81.275,55.807 81.275,54.6 80.9,54.225 80.475,54.225 80.227,53.977 80.227,53.55 81.025,52.752 81.025,52.075 80.19,51.24 80.19,45.06 82.07,43.179 v1(82.07,42.38)
  Bottom w0.127: R158.1@44.48,51.15 44.728,50.902 v1(45.36,50.902)
PCM_OUT: J20.21 R157.1 U1.F13 | length 150.9
  Top w0.127: U1.F13@82.72,43.04 83.45,43.77 83.443,43.777 v1(83.379,43.777)
  Signal_4 w0.142: v1(20.975,62.75) 21.05,62.75 21.794,63.494 23.931,63.494 v1(24.6,62.825)
  Signal_7 w0.142: J20.21@3.965,34.925 3.9,34.925 2.825,36 2.825,43.225 3.598,43.998 12.177,43.998 13.437,45.257 13.437,49.848 13.435,49.85 13.435,51.11 15.61,53.285 15.763,53.285 18.1,55.623 18.1,58.952 19.987,60.839 19.987,61.687 20.975,62.675 v1(20.975,62.75) ; v1(24.6,62.825) 27.971,62.825 29.603,64.457 38.777,64.457 ; v1(41.35,53.9) 40.875,53.425 40.15,53.425 39.846,53.729 39.846,54.929 39.3,55.475 39.3,57.225 40.825,58.75 40.825,59.148 38.777,61.197 38.777,64.457 ; v1(83.379,43.777) 82.619,43.777 82.617,43.775 81.647,44.745 81.647,45.197 82.612,46.162 82.612,52.887 83.118,53.393 83.118,54.243 83.831,54.956 83.831,57.602 82.425,59.008 82.425,61.51 81.455,62.48 81.455,63.105 82.45,64.1 83.898,64.1 84.448,64.65 84.448,65 84.2,65.248 84.189,65.248 84.163,65.274 76.566,65.274 75.048,66.792 69.943,66.792 69.558,66.408 69.171,66.408 66.463,63.7 64.975,63.7 63.719,64.956 42.454,64.956 41.955,64.457 38.777,64.457
  Bottom w0.127: R157.1@41.2,53.255 41.35,53.405 v1(41.35,53.9)
PCM_SYNC: J20.22 R156.1 U1.F14 | length 113.2
  Top w0.127: U1.F14@82.72,41.77 83.33,42.38 83.333,42.377 v1(83.379,42.377)
  Signal_4 w0.142: J20.22@1.46,34.92 2.848,36.308 9.908,36.308 10.763,37.163 10.763,38.979 10.714,39.029 10.714,40.455 14.45,44.191 20.394,44.191 20.703,44.5 23.525,44.5 24.225,43.8 30.039,43.8 30.739,44.5 33.025,44.5 34.375,43.15 36.475,43.15 38.275,44.95 40.225,44.95 44.6,49.325 v1(45.15,49.325)
  Signal_7 w0.142: v1(45.15,49.325) 45.85,50.025 49.025,50.025 51.2,52.2 51.2,54.466 51.28,54.545 ; 51.287,54.538 53.849,57.099 57.766,57.099 57.849,57.182 58.418,57.751 79.082,57.751 79.651,57.182 79.651,42.674 80.368,41.957 82.917,41.957 83.337,42.377 v1(83.379,42.377)
  Bottom w0.127: R156.1@44.48,49.3 44.505,49.325 v1(45.15,49.325)
POR_B: CAD1.10 U1.AH10 | length 55
  Top w0.127: v1(54.17,47.47) 54.17,47.46 U1.AH10@54.78,46.85
  Signal_7 w0.142: v1(36.68,22.76) 37.732,21.708 41.225,21.708 43.144,19.788 44.888,19.788 45.075,19.975 45.923,19.975 46.712,19.187 51.369,19.187 53.539,21.356 54.056,21.356 57.217,24.517 57.217,29.858 56.144,30.931 56.144,46.406 55.8,46.75 54.9,46.75 54.895,46.745 v1(54.17,47.47)
  Bottom w0.127: v1(36.68,22.76) 36.68,23.529 36.034,24.175 36.034,24.947 36.33,25.242 36.354,25.242 37.416,26.303 37.893,26.303 CAD1.10@38,26.41
POWER_BUTTON: J20.40 R13.1 R213.1 SW1.3 SW1.4 | length 32.6
  Top w0.127: J20.40@1.46,12.06 2.664,13.264 4.689,13.264 5.15,13.725 5.15,15.359 5.84,16.049 11.987,16.049 17.434,21.497 17.434,22.222 17.678,22.465 18.022,22.465 19.02,23.463 SW1.3@19.02,24.2 ; R213.1@13.635,26.3 13.635,24.535 SW1.4@13.3,24.2 16.152,24.2 16.348,24.004 16.692,24.004 16.888,24.2 SW1.3@19.02,24.2 ; SW1.3@19.1,24.2 SW1.3@19.02,24.2
POWER_LED: Q8.G R216.1 U1.AL22 | length 27.1
  Top w0.127: v1(35.25,26.5) R216.1@35.25,27.2 Q8.G@35.25,28.21 ; v1(50.35,31) 50.36,31 U1.AL22@50.97,31.61
  Signal_8 w0.142: v1(35.25,26.5) 35.212,26.538 35.212,29.612 37.263,31.663 43.337,31.663 43.7,31.3 44.35,31.3 44.675,31.625 46.65,31.625 48.098,30.177 48.098,28.192 48.4,27.89 49.169,27.89 49.6,28.321 49.6,30.25 v1(50.35,31)
PWR_ON: R64.2 U1.AJ12 | length 56.4
  Top w0.127: v1(52.9,43.675) 52.9,43.7 U1.AJ12@53.51,44.31
  Signal_8 w0.142: v1(52.9,43.675) 53.557,43.675 54.932,42.3 54.932,41.893 55.15,41.675 56.635,41.675 56.65,41.69 57.231,41.109 57.231,33.046 56.775,32.59 56.775,32.11 57.325,31.56 57.325,23.4 57.776,22.949 80.551,22.949 81,22.5 82.127,22.5 83.225,21.402 85.782,21.402 86.705,22.325 v1(87.175,22.325)
  Bottom w0.127: v1(87.175,22.325) 87.175,21.705 R64.2@87.2,21.68
QOW: J20.25 U1.F23 | length 100.3
  Top w0.127: v1(82.1,29.73) 82.11,29.73 U1.F23@82.72,30.34
  Signal_4 w0.142: J20.25@4,29.84 5.465,28.375 5.465,23.975 6.04,23.4 9.45,23.4 10.327,22.523 13.125,22.523 13.7,21.948 13.7,21.35 14.325,20.725 16.35,20.725 16.832,21.207 v1(19.295,21.207)
  Signal_7 w0.142: v1(19.295,21.207) 19.295,21.225 20.295,20.225 22.015,20.225 23.765,18.475 25.248,18.475 26.865,16.858 30.037,16.858 30.442,17.263 30.442,17.265 31.435,18.258 34.483,18.258 35.675,19.45 35.675,20.698 36.2,21.223 36.625,21.223 36.679,21.169 40.831,21.169 42.75,19.25 44.65,19.25 45.252,18.648 51.592,18.648 53.762,20.817 54.512,20.817 54.61,20.719 55.404,20.719 57.6,22.915 81.795,22.915 82.08,23.2 82.08,23.84 81.52,24.4 81.52,29.15 v1(82.1,29.73)
RF_KILL: R10.1 U1.B16 U1.B17 U1.G29 | length 29.4
  Top w0.127: U1.G29@81.45,22.72 81.775,22.395 v1(81.775,21.125) ; U1.B16@87.8,39.23 U1.B17@87.8,37.96 88.41,37.35 v1(88.41,37.34)
  Signal_8 w0.142: v1(81.775,21.125) 82.048,20.852 87.052,20.852 v1(90.5,24.3)
  Signal_7 w0.142: v1(88.41,37.34) 89.11,36.64 89.11,36.01 90.489,34.631 90.489,27.931 91.12,27.3 91.12,25.82 90.5,25.2 v1(90.5,24.3)
  Bottom w0.127: R10.1@81.55,21.82 81.575,21.82 81.796,21.599 81.796,21.146 v1(81.775,21.125)
"RGMII1_INT_ B": R16.2 U1.AA1 U9.6 | length 69.6
  Top w0.127: v1(63.1,59.075) 63.1,58.85 U1.AA1@63.67,58.28
  Signal_3 w0.142: v1(20.725,38.5) 20.25,38.975 20.25,39.35 19.946,39.654 19.946,40.013 19.706,40.253 19.706,43.16 20.25,43.704 20.25,47.052 20.177,47.125 20.177,47.475 20.25,47.548 20.25,49.802 20.227,49.825 20.227,53.752 21.55,55.075 v1(21.55,56.15)
  Signal_4 w0.142: v1(21.55,56.15) 22.375,55.325 23.05,55.325 23.85,54.525 24.719,54.525 25.283,55.088 26.829,55.088 27.548,54.369 30.326,54.369 32.175,56.218 33.778,56.218 34.96,57.4 35.66,57.4 39.229,60.969 42.51,60.969 43.162,61.621 51.758,61.621 52.026,61.353 52.026,61.349 53.428,59.947 53.428,59.472 54.483,58.417 57.932,58.417 58.141,58.625 62.65,58.625 v1(63.1,59.075)
  Bottom w0.127: v1(20.725,38.5) 20.425,38.8 20.425,39.07 R16.2@20.5,39.07 20.545,39.07 20.975,39.5 U9.6@21.52,39.5
"RGMII1_INT_ B_1V8": R74.1 U9.1 U11.5 | length 19.8
  Signal_8 w0.142: v1(23.025,39.925) 23.025,39.552 25.426,37.151 27.474,37.151 30.775,33.85 32.075,33.85 32.95,32.975 v1(32.95,32.825)
  Bottom w0.127: v1(23.025,39.925) 23.025,39.555 U9.1@23.08,39.5 ; U11.5@28.49,30.792 29.273,30.792 30.706,32.225 32.35,32.225 v1(32.95,32.825) 32.95,33.382 R74.1@33.16,33.592
RGMII1_RD0: R86.1 R87.2 U1.A16 U11.31 | length 138.7
  Top w0.127: U1.A16@89.07,39.23 89.68,38.62 v1(89.68,38.61)
  Signal_8 w0.142: v1(20.975,37.4) 21.363,37.788 21.363,42.238 20.975,42.627 20.727,42.875 20.727,44.075 22.2,45.548 22.2,46.95 23.471,48.221 23.471,49.707 24.864,51.1 27.125,51.1 28.073,52.048 28.073,57.673 28.88,58.48 29.596,58.48 30.988,59.872 30.988,60.748 30.05,61.686 29.554,61.686 29.1,62.14 29.1,66.525 30.644,68.069 33.759,68.069 34.354,68.663 42.587,68.663 43.301,67.949 51.438,67.949 51.55,68.061 51.622,68.061 52.418,68.062 53.275,68.061 53.495,67.842 53.638,67.842 53.688,67.792 57.406,67.792 57.675,68.061 59.312,68.061 59.359,68.015 65.516,68.015 66.125,68.623 66.475,68.623 66.688,68.411 67.803,68.411 67.812,68.419 85.881,68.419 89.094,65.206 89.094,63.615 89.579,63.13 89.626,63.13 89.927,62.829 89.927,58.848 91.495,57.28 91.495,51.351 92.556,50.29 92.556,43.825 90.262,41.531 90.262,41.439 90.2,41.377 90.2,39.13 v1(89.68,38.61)
  Bottom w0.127: 21.193,37.338 21.415,37.116 21.415,36.268 20.94,35.792 R87.2@20.915,35.792 20.89,35.792 20.414,35.317 20.414,34.398 20.466,34.347 20.466,33.962 20.23,33.727 20.23,32.338 22.067,30.502 22.16,30.502 22.27,30.392 U11.31@22.59,30.392
RGMII1_RD1: R88.1 R89.2 U1.A15 U11.30 | length 141.5
  Top w0.127: U1.A15@89.07,40.5 89.68,39.89 v1(89.68,39.88)
  Signal_8 w0.142: v1(20.65,31.3) 22.95,31.3 24.775,33.125 24.775,34.221 21.633,37.363 21.633,44.383 22.525,45.275 22.525,46.894 23.74,48.11 23.74,49.596 24.968,50.823 27.323,50.823 28.342,51.842 28.342,56.542 32.025,60.225 32.025,60.778 32.1,60.853 32.1,61.25 30.975,62.375 30.975,64.994 31.96,65.979 31.96,66.94 32.819,67.8 33.871,67.8 34.465,68.394 41.117,68.394 41.831,67.68 51.549,67.68 51.661,67.792 51.733,67.792 52.307,67.792 ; 52.307,67.792 53.163,67.792 53.383,67.572 53.527,67.572 53.576,67.523 57.517,67.523 57.787,67.792 59.2,67.792 59.247,67.746 67.519,67.746 67.923,68.15 81.067,68.15 82.51,66.708 87.156,66.708 88.825,65.038 88.825,63.503 89.468,62.861 89.514,62.861 89.658,62.717 89.658,58.648 91.225,57.081 91.225,42.876 89.992,41.643 89.992,41.55 89.68,41.238 v1(89.68,39.88)
  Bottom w0.127: R89.2@19.89,35.792 19.865,35.792 19.389,35.317 19.389,33.792 19.976,33.205 19.976,31.974 v1(20.65,31.3) 21.125,30.825 21.239,30.825 22.036,30.029 22.553,30.029 U11.30@22.59,29.992
RGMII1_RD2: R94.1 R95.2 U1.A14 U11.28 | length 141.8
  Top w0.127: U1.A14@89.07,41.77 v1@89.68,42.38 ; v1@89.679,42.381 v1(89.679,42.452)
  Signal_8 w0.142: v1(21.575,29.2) 25.075,32.7 25.075,35.345 24.176,36.244 24.176,38.02 21.902,40.294 21.902,44.252 22.85,45.2 22.85,46.838 25.473,49.462 27.037,49.462 28.612,51.037 28.612,55.462 29.56,56.41 29.56,56.821 30.114,57.375 30.7,57.375 31.165,57.84 31.165,58.985 32.294,60.113 32.294,60.667 32.369,60.741 32.369,61.362 31.244,62.487 31.244,63.894 33.45,66.1 33.45,66.998 34.577,68.125 41.006,68.125 41.72,67.411 51.733,67.411 51.845,67.523 52.195,67.523 53.052,67.523 53.272,67.303 53.415,67.303 53.465,67.254 57.629,67.254 57.898,67.523 59.089,67.523 59.136,67.476 60.51,67.476 61.202,66.785 61.202,66.775 61.233,66.775 61.253,66.755 63.084,66.755 63.737,67.408 68.133,67.408 68.6,67.875 80.962,67.875 82.398,66.438 86.062,66.438 88.1,64.4 88.1,63.575 87.644,63.119 87.644,61.606 89.388,59.862 89.388,58.537 90.956,56.969 90.956,43.656 89.752,42.452 v1(89.679,42.452)
  Bottom w0.127: R95.2@18.865,35.792 18.84,35.792 18.364,35.317 18.364,34.048 18.778,33.634 19.135,33.634 19.642,33.127 19.642,31.73 19.4,31.487 19.4,29.013 19.728,28.684 21.059,28.684 v1(21.575,29.2) 22.582,29.2 U11.28@22.59,29.192
RGMII1_RD3: R98.1 R99.2 U1.A13 U11.27 | length 141.7
  Top w0.127: U1.A13@89.07,43.04 89.68,43.65 89.678,43.652 v1(89.629,43.652)
  Signal_8 w0.142: v1(16.801,34.102) 16.801,34.416 16.949,34.564 16.949,35.302 16.9,35.351 16.9,35.719 16.981,35.799 16.981,39.111 16.35,39.742 16.35,40.925 17.548,42.123 17.548,45.598 18.269,46.319 18.269,50.03 20.989,52.749 22.63,52.749 23.025,53.144 23.025,55.691 23.61,56.277 23.61,59.46 24.473,60.323 24.473,61.35 26.677,63.554 26.677,67.877 v1(26.925,68.125) ; v1(34.3,67.25) 34.575,66.975 36.104,66.975 36.904,67.775 40.925,67.775 41.575,67.125 45.05,67.125 45.75,66.425 48.125,66.425 48.8,67.1 50.497,67.1 51.14,66.457 53.415,66.457 53.943,66.984 57.74,66.984 58.01,67.254 58.977,67.254 59.024,67.207 60.399,67.207 60.683,66.923 60.683,66.913 61.121,66.475 63.185,66.475 63.848,67.138 68.363,67.138 68.75,67.525 80.931,67.525 82.287,66.169 85.931,66.169 87.8,64.3 87.8,63.725 87.375,63.3 87.375,61.475 89.119,59.731 89.119,58.381 90.687,56.813 90.687,44.647 89.692,43.652 v1(89.629,43.652)
  Signal_4 w0.142: v1(26.925,68.125) 27.023,68.027 32.798,68.027 33.575,67.25 v1(34.3,67.25)
  Bottom w0.127: R99.2@17.84,35.792 17.815,35.792 16.801,34.778 v1(16.801,34.102) 16.801,34.099 17.52,33.38 19.03,33.38 19.388,33.022 19.388,31.835 19.146,31.592 19.146,28.908 19.623,28.43 21.39,28.43 21.736,28.777 22.574,28.777 U11.27@22.59,28.792
RGMII1_RESET_N: U1.AG11 U11.2 | length 48.4
  Top w0.127: v1(55.44,46.2) 55.44,46.19 U1.AG11@56.05,45.58
  Signal_8 w0.142: v1(29.16,32.76) 29.265,32.76 30.3,31.725 33.675,31.725 34.525,32.575 34.525,35.05 33.875,35.7 33.875,38.825 36.18,41.13 36.18,47.43 37.773,49.023 43.976,49.023 47.574,45.425 51.893,45.425 53.06,44.258 54.558,44.258 55.023,44.723 55.625,44.723 55.628,44.72 55.643,44.72 55.883,44.96 55.883,45.757 v1(55.44,46.2)
  Bottom w0.127: U11.2@28.49,31.992 28.81,31.992 28.919,32.102 28.974,32.102 29.16,32.287 v1(29.16,32.76)
RGMII1_RX_CTL: R92.1 R93.2 U1.A17 U11.32 | length 142.6
  Top w0.127: U1.A17@89.07,37.96 89.68,37.35 v1(89.68,37.34)
  Signal_8 w0.142: v1(21.425,33.925) 21.425,35.426 20.137,36.714 20.137,43.562 20.429,43.854 20.429,46.004 21.05,46.625 21.475,46.625 23.202,48.352 23.202,49.819 25.229,51.846 25.229,54.033 27.065,55.87 27.065,58.254 27.561,58.749 29.485,58.749 30.719,59.983 30.719,60.637 29.939,61.417 29.442,61.417 28.831,62.028 28.831,66.637 30.533,68.338 33.648,68.338 34.282,68.973 43.602,68.973 44.356,68.219 51.326,68.219 51.438,68.331 51.51,68.331 52.53,68.331 53.386,68.331 53.606,68.111 53.75,68.111 53.799,68.061 55.344,68.061 55.363,68.081 55.587,68.081 55.606,68.061 57.294,68.061 57.564,68.331 59.423,68.331 59.47,68.284 65.405,68.284 66.013,68.892 66.587,68.892 66.799,68.68 67.691,68.68 67.7,68.688 86.012,68.688 90.883,63.817 90.883,62.86 90.881,62.858 90.881,60.119 91.15,59.85 91.15,58.04 91.764,57.426 91.764,51.463 92.825,50.402 92.825,43.714 90.531,41.419 90.531,41.327 90.5,41.296 90.5,38.16 v1(89.68,37.34)
  Bottom w0.127: v1(21.425,33.925) 21.365,33.865 20.728,33.865 20.484,33.622 20.484,32.444 22.1,30.829 22.553,30.829 U11.32@22.59,30.792 ; v1@21.425,33.985 21.425,35.302 21.915,35.792 R93.2@21.94,35.792
RGMII1_RXC: R96.1 R97.2 U1.A18 U11.33 | length 148
  Top w0.127: U1.A18@89.07,36.69 89.68,36.08 v1(89.68,36.07)
  Signal_8 w0.142: v1(20.9,33.45) 20.475,33.875 20.475,34.631 19.898,35.207 19.898,35.783 19.867,35.813 19.867,43.733 20.16,44.025 20.16,47.483 20.85,48.173 21.2,48.173 21.498,47.875 22.15,47.875 22.933,48.658 22.933,49.931 24.96,51.957 24.96,54.145 26.796,55.981 26.796,58.365 27.449,59.018 29.373,59.018 30.45,60.095 30.45,60.525 29.827,61.148 29.331,61.148 28.562,61.917 28.562,66.748 30.492,68.678 33.607,68.678 34.171,69.242 43.733,69.242 44.487,68.488 51.215,68.488 51.327,68.6 51.398,68.6 52.641,68.6 53.498,68.6 53.718,68.38 53.861,68.38 53.911,68.331 55.233,68.331 55.363,68.461 55.587,68.461 55.717,68.331 57.183,68.331 57.452,68.6 59.535,68.6 59.582,68.553 65.293,68.553 65.902,69.162 66.698,69.162 66.911,68.949 67.58,68.949 67.588,68.958 88.996,68.958 89.925,68.028 89.925,67.3 91.419,65.806 91.419,65.742 91.421,65.74 91.421,65.06 91.419,65.058 91.419,58.152 92.033,57.538 92.033,53.192 93.1,52.125 93.1,43.608 90.8,41.308 90.8,37.19 v1(89.68,36.07)
  Bottom w0.127: U11.33@22.59,31.192 22.553,31.229 22.059,31.229 20.9,32.387 v1(20.9,33.45) 21.888,33.45 22.491,34.053 22.491,34.397 22.464,34.423 22.464,35.317 22.94,35.792 R97.2@22.965,35.792
RGMII1_TD0: U1.A22 U11.36 | length 164.6
  Top w0.127: U1.A22@89.07,31.61 89.68,31 v1(89.68,30.99)
  Signal_8 w0.142: v1(22.6,32.875) 22.6,32.396 21.837,31.633 20.916,31.633 20.667,31.882 18.766,31.882 17.55,33.097 17.55,33.375 17.303,33.622 17.303,34.537 17.275,34.565 17.275,39.95 18.252,40.927 18.252,44.402 18.538,44.688 18.538,49.918 21.1,52.48 22.741,52.48 23.294,53.033 23.294,55.58 23.888,56.174 23.888,58.288 24.945,59.345 24.945,61.441 26.946,63.443 26.946,67.448 29.233,69.734 29.24,69.734 30.475,70.969 52.344,70.969 52.394,70.919 62.158,70.919 62.598,70.479 64.934,70.479 65.233,70.777 67.367,70.777 67.571,70.573 89.975,70.573 94.002,66.546 94.002,64.315 93.094,63.408 93.094,60.481 94.073,59.502 94.073,58.867 93.649,58.443 93.649,56.301 94.925,55.025 94.925,52.875 96.206,51.594 96.206,44.429 94.775,42.998 94.775,40.195 92.52,37.94 92.52,30.692 89.855,28.027 89.505,28.027 89.257,28.275 89.257,30.567 v1(89.68,30.99)
  Bottom w0.127: U11.36@22.59,32.392 22.6,32.402 v1(22.6,32.875)
RGMII1_TD1: U1.A21 U11.37 | length 151.9
  Top w0.127: U1.A21@89.07,32.88 89.68,32.27 v1(89.68,32.26)
  Signal_8 w0.142: v1(22.825,33.5) 21.979,33.5 21.322,32.843 21.305,32.843 21.219,32.758 20.467,32.758 19.331,33.894 19.331,35.294 18.083,36.542 18.083,39.502 19.06,40.479 19.06,44.067 19.346,44.354 19.346,47.812 20.921,49.387 21.807,49.387 22.125,49.705 22.125,50.265 24.102,52.242 24.102,55.245 24.35,55.493 24.985,55.493 25.988,56.496 25.988,60.069 26.345,60.426 26.345,61.699 27.754,63.108 27.754,67.106 30.809,70.162 48.176,70.162 48.93,69.408 51.064,69.408 52.976,69.408 53.832,69.408 54.052,69.188 54.196,69.188 54.245,69.138 54.898,69.138 55.168,69.408 55.782,69.408 56.052,69.138 56.848,69.138 57.118,69.408 59.87,69.408 59.916,69.361 64.959,69.361 65.567,69.969 67.033,69.969 67.245,69.757 67.254,69.765 89.64,69.765 93.194,66.212 93.194,64.679 92.227,63.712 92.227,58.486 92.841,57.873 92.841,55.967 94.117,54.69 94.117,52.54 95.398,51.26 95.398,44.764 91.608,40.973 91.608,34.188 v1(89.68,32.26)
  Bottom w0.127: v1(22.825,33.5) 22.838,33.487 23.303,33.487 23.34,33.45 U11.37@23.34,33.142
RGMII1_TD2: U1.A20 U11.38 | length 151.1
  Top w0.127: U1.A20@89.07,34.15 89.68,33.54 v1(89.68,33.53)
  Signal_8 w0.142: v1(23.6,33.9) 23.6,34.55 23.4,34.75 22.725,34.75 22.5,34.525 22.5,33.975 22.294,33.769 21.868,33.769 21.211,33.112 21.193,33.112 21.108,33.027 20.579,33.027 19.627,33.979 19.627,34.35 19.629,34.352 19.629,35.671 18.352,36.948 18.352,39.39 19.329,40.367 19.329,43.956 19.615,44.242 19.615,47.7 21.032,49.117 21.918,49.117 22.394,49.593 22.394,50.154 24.421,52.18 24.421,54.368 26.258,56.204 26.258,59.958 26.614,60.314 26.614,61.587 28.023,62.996 28.023,66.994 30.921,69.892 48.064,69.892 48.818,69.138 51.175,69.138 52.864,69.139 53.721,69.138 53.941,68.919 54.084,68.919 54.134,68.869 55.01,68.869 55.279,69.138 55.671,69.138 55.94,68.869 56.96,68.869 57.229,69.138 59.758,69.138 59.805,69.092 65.07,69.092 65.679,69.7 66.921,69.7 67.134,69.488 67.357,69.488 67.365,69.496 89.529,69.496 92.925,66.1 92.925,64.79 91.958,63.823 91.958,58.375 92.572,57.761 92.572,55.855 93.848,54.579 93.848,52.429 95.129,51.148 95.129,44.875 91.338,41.085 91.338,35.188 v1(89.68,33.53)
  Bottom w0.127: v1(23.6,33.9) 23.6,33.813 23.74,33.673 U11.38@23.74,33.142
RGMII1_TD3: U1.A19 U11.39 | length 144.7
  Top w0.127: U1.A19@89.07,35.42 89.68,34.81 v1(89.68,34.8)
  Signal_8 w0.142: v1(19.3,37.85) 19.33,37.85 19.598,38.118 19.598,43.844 19.89,44.137 19.89,47.595 21.144,48.848 22.03,48.848 22.663,49.482 22.663,50.042 24.69,52.069 24.69,54.256 26.527,56.093 26.527,58.477 27.548,59.498 27.548,60.853 27.402,61 27.402,61.777 28.292,62.667 28.292,66.883 31.033,69.623 47.952,69.623 48.706,68.869 51.287,68.869 ; 51.287,68.869 52.753,68.869 53.609,68.869 53.829,68.649 53.973,68.649 54.022,68.6 55.121,68.6 55.391,68.869 55.559,68.869 55.829,68.6 57.071,68.6 57.341,68.869 59.647,68.869 59.693,68.823 65.182,68.823 65.79,69.431 66.81,69.431 67.022,69.218 67.468,69.218 67.477,69.227 89.121,69.227 90.2,68.148 90.2,67.406 91.69,65.915 91.69,64.948 91.688,64.946 91.688,58.263 92.302,57.649 92.302,55.744 93.579,54.467 93.579,52.317 94.85,51.046 94.85,45.59 94.86,45.581 94.86,44.987 91.069,41.196 91.069,36.189 v1(89.68,34.8)
  Signal_7 w0.142: v1(19.3,37.85) 19.349,37.801 19.349,37.101 20.475,35.975 23.25,35.975 24.2,35.025 v1(24.2,33.94)
  Bottom w0.127: U11.39@24.14,33.142 24.14,33.88 v1(24.2,33.94)
RGMII1_TX_CTL: U1.A23 U11.34 | length 155.7
  Top w0.127: U1.A23@89.07,30.34 89.68,29.73 v1(89.68,29.72)
  Signal_8 w0.142: v1(21.48,32.42) 20.382,32.42 19.259,33.542 18.638,33.542 18.428,33.753 18.428,35.322 17.813,35.936 17.813,39.613 18.79,40.59 18.79,44.179 19.077,44.465 19.077,49.025 20.562,50.511 20.708,50.511 21.372,51.174 22.653,51.174 23.833,52.353 23.833,55.357 24.238,55.762 24.874,55.762 25.719,56.608 25.719,60.181 26.076,60.537 26.076,61.81 27.485,63.219 27.485,67.217 30.698,70.431 52.121,70.431 52.871,69.68 53.941,69.68 54.164,69.457 54.307,69.457 54.357,69.408 54.787,69.408 55.056,69.677 55.894,69.677 56.163,69.408 56.737,69.408 57.006,69.677 59.981,69.677 60.028,69.63 64.847,69.63 65.456,70.239 67.144,70.239 67.348,70.035 89.752,70.035 93.463,66.323 93.463,64.538 92.496,63.571 92.496,58.598 93.11,57.984 93.11,56.078 94.387,54.802 94.387,52.652 95.667,51.371 95.667,44.652 94.237,43.221 94.237,41.937 91.877,39.577 91.877,31.917 v1(89.68,29.72)
  Bottom w0.127: v1(21.48,32.42) 21.48,32.327 22.106,31.702 22.16,31.702 22.27,31.592 U11.34@22.59,31.592
RGMII1_TXC: U1.A24 U11.35 | length 160.3
  Top w0.127: U1.A24@89.07,29.07 89.68,28.46 v1(89.68,28.45)
  Signal_8 w0.142: v1(21.975,32.875) 21.975,32.152 21.725,31.902 21.027,31.902 20.778,32.151 20.27,32.151 19.148,33.273 18.527,33.273 18.159,33.641 18.159,35.166 17.544,35.781 17.544,39.823 18.521,40.8 18.521,44.29 18.808,44.577 18.808,49.137 20.451,50.78 20.597,50.78 21.261,51.444 22.542,51.444 23.563,52.465 23.563,55.468 24.127,56.032 24.762,56.032 25.45,56.719 25.45,60.292 25.806,60.649 25.806,61.922 27.215,63.331 27.215,67.329 30.586,70.7 52.232,70.7 52.406,70.527 53.475,70.527 54.275,69.726 54.419,69.726 54.468,69.677 54.675,69.677 54.945,69.946 56.005,69.946 56.275,69.677 56.625,69.677 56.894,69.946 57.598,69.946 58.301,70.65 62.046,70.65 62.486,70.21 65.046,70.21 65.344,70.508 67.256,70.508 67.46,70.304 89.863,70.304 93.733,66.435 93.733,64.427 92.825,63.519 92.825,60.325 93.804,59.346 93.804,58.979 93.379,58.554 93.379,56.19 94.656,54.913 94.656,52.763 95.937,51.483 95.937,44.541 94.506,43.11 94.506,40.307 92.251,38.052 92.251,31.021 v1(89.68,28.45)
  Bottom w0.127: v1(21.975,32.875) 21.975,32.232 22.106,32.102 22.16,32.102 22.27,31.992 U11.35@22.59,31.992
"RGMII2_INT_ B": R80.2 U1.AE1 U9.3 | length 53.3
  Top w0.127: v1(57.703,59.178) 57.703,59.167 U1.AE1@58.59,58.28
  Signal_8 w0.142: v1(25.025,38.175) 24.852,38.348 24.852,40.793 25.703,41.644 28.719,41.644 30.125,43.05 30.875,43.05 31.205,43.38 31.205,45.553 32.625,46.974 32.625,47.552 32.648,47.552 38.423,53.328 38.423,56.137 38.1,56.46 38.1,57.925 41.344,61.169 42.71,61.169 43.142,61.601 49.275,61.601 50.851,60.025 56.75,60.025 57.655,59.12 57.703,59.168 v1(57.703,59.178)
  Bottom w0.127: U9.3@23.08,38.5 24.18,38.5 R80.2@24.2,38.52 24.545,38.175 v1(25.025,38.175)
"RGMII2_INT_ B_1V8": R106.1 U9.4 U12.5 | length 12.2
  Top w0.127: v1(28.46,38.36) 28.46,39.81 U12.5@28.5,39.85
  Signal_4 w0.142: v1@20.62,37.9 21.375,37.9 21.925,38.45 23.675,38.45 24.475,37.65 27.725,37.65 28.435,38.36 v1(28.46,38.36)
  Bottom w0.127: v1@20.62,37.9 21.275,37.9 21.52,38.145 U9.4@21.52,38.5 ; v1(28.46,38.36) 28.46,38.49 28.77,38.8 R106.1@28.87,38.8
  other v1: 20.575,37.925
RGMII2_RD0: R118.1 R119.2 U1.D21 U12.31 | length 116.7
  Top w0.127: R119.2@23.225,47.4 23.225,47.425 23.701,47.9 23.701,48.78 23.821,48.9 25.104,48.9 25.73,48.275 v1(27.175,48.275) 27.175,48.231 28.575,46.831 28.575,46.512 28.864,46.224 28.864,45.786 U12.31@28.9,45.75 ; U1.D21@85.26,32.88 85.87,32.27 v1(85.87,32.26)
  Signal_8 w0.142: v1(27.175,48.275) 25.575,48.275 23.669,46.369 23.669,45.806 24.707,44.768 27.027,44.768 27.259,45 29.462,45 31.183,46.72 31.183,47.323 31.95,48.091 32.425,48.091 33.401,49.067 33.401,51.689 35.306,53.594 35.306,54.803 37.023,56.52 37.023,59.484 40.362,62.823 52.217,62.823 52.715,62.325 59.827,62.325 60.325,62.823 62.138,62.823 63.665,61.296 71.843,61.296 72.008,61.131 81.806,61.131 82.688,60.248 82.688,58.542 84.096,57.134 84.096,33.435 84.631,32.9 85.23,32.9 v1(85.87,32.26)
RGMII2_RD1: R120.1 R121.2 U1.D23 U12.30 | length 104.2
  Top w0.127: R121.2@23.2,48.3 R121.2@23.263,48.362 ; R121.2@23.225,48.4 23.447,48.621 23.447,48.885 23.716,49.154 25.489,49.154 25.953,48.691 27.347,48.691 28.997,47.041 28.997,46.678 v1(29.025,46.65) 29.025,46.563 29.264,46.324 29.264,45.786 U12.30@29.3,45.75 ; U1.D23@85.26,30.34 85.875,29.725 85.876,29.726 v1(85.904,29.726)
  Signal_8 w0.142: v1(35.475,51.325) 35.5,51.325 37.54,53.365 37.54,54.911 38.117,55.488 38.117,56.062 37.831,56.348 37.831,58.172 41.097,61.438 42.598,61.438 43.03,61.87 51.675,61.87 53.062,60.483 66.195,60.483 66.355,60.323 78.458,60.323 79.175,59.606 79.175,59.2 79.981,58.394 81.629,58.394 82.299,57.724 ; 82.31,57.735 82.612,57.433 82.612,32.363 85.249,29.726 v1(85.904,29.726)
  Signal_4 w0.142: v1(29.025,46.65) 29.025,47.305 29.397,47.677 31.827,47.677 v1(35.475,51.325)
RGMII2_RD2: R126.1 R127.2 U1.C20 U12.28 | length 113.3
  Top w0.127: R127.2@23.225,49.625 R127.2@23.225,49.675 23.225,49.7 23.7,50.175 23.7,51.075 23.8,51.175 24.691,51.175 25.31,50.555 25.31,49.98 25.236,49.905 25.236,49.767 26.059,48.945 27.721,48.945 28.691,47.975 v1(28.7,47.975) 28.841,48.115 28.841,48.953 29.403,49.516 29.747,49.516 30.1,49.163 U12.28@30.1,45.75 ; U1.C20@86.53,34.15 87.14,33.54 v1(87.14,33.53)
  Signal_8 w0.142: v1(28.7,47.975) 29.9,47.975 31.697,49.772 31.697,52.992 32.182,53.477 32.255,53.477 32.503,53.725 32.503,54.075 33.96,55.533 33.96,56.418 35.027,57.485 35.027,60.679 36.738,62.39 36.738,63.402 37.237,63.9 51.39,63.9 52.013,64.523 53.873,64.523 ; 53.873,64.523 55.339,64.523 55.404,64.588 55.64,64.588 55.72,64.509 59.824,64.509 59.905,64.59 60.266,64.59 60.308,64.548 61.937,64.548 63.438,63.046 68.634,63.046 69,62.68 72.32,62.68 72.775,62.225 82.706,62.225 85.131,59.8 85.558,59.8 86.675,58.683 86.675,33.995 v1(87.14,33.53)
RGMII2_RD3: R130.1 R131.2 U1.B22 U12.27 | length 119
  Top w0.127: R131.2@23.2,50.625 23.446,50.872 23.446,51.181 23.695,51.429 24.796,51.429 25.564,50.661 25.564,49.798 26.164,49.199 27.926,49.199 28.025,49.1 v1(28.425,49.1) 28.628,49.1 29.298,49.77 29.852,49.77 30.5,49.122 U12.27@30.5,45.75 ; U1.B22@87.8,31.61 88.41,31 v1(88.41,30.99)
  Signal_8 w0.142: v1(28.425,49.1) 29.071,49.746 30.067,49.746 30.811,50.49 30.811,54.411 34.219,57.819 34.219,61.013 35.825,62.619 35.825,63.631 36.902,64.708 51.056,64.708 51.678,65.331 53.812,65.331 53.878,65.396 54.142,65.396 54.207,65.331 55.004,65.331 55.07,65.396 55.975,65.396 56.054,65.317 59.489,65.317 59.57,65.397 60.6,65.397 60.642,65.356 61.833,65.356 61.874,65.397 63.437,65.397 64.89,63.944 70.394,63.944 71.412,64.962 77.188,64.962 78.412,63.738 85.524,63.738 86.265,62.998 86.265,60.235 87.483,59.017 87.483,56.545 88.15,55.878 88.15,51.044 88.843,50.35 88.843,49.825 88.833,49.814 88.833,47.238 88.843,47.228 88.843,33.365 87.987,32.508 87.987,31.413 v1(88.41,30.99)
RGMII2_RESET_N: U1.AG12 U12.2 | length 41.3
  Top w0.127: v1(25.775,39.85) 26.385,39.24 27.064,39.24 27.3,39.475 U12.2@27.3,39.85 ; v1(55.46,45.16) 55.46,44.9 U1.AG12@56.05,44.31
  Signal_8 w0.142: v1(25.775,39.85) 25.775,40.625 26.525,41.375 28.9,41.375 30.3,42.775 31,42.775 31.64,43.415 31.64,44.54 34.075,46.975 34.075,47.727 33.877,47.925 33.877,48.275 34.894,49.292 44.088,49.292 47.686,45.694 52.004,45.694 53.172,44.527 54.377,44.527 55.01,45.16 v1(55.46,45.16)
